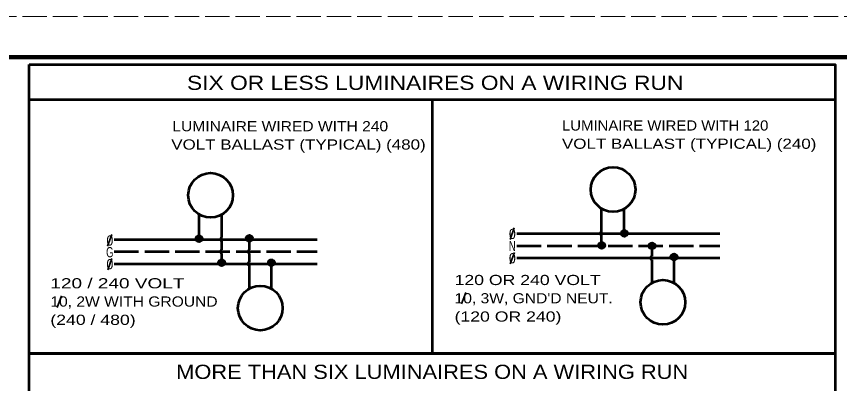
# Model space of a CAD drawing. Extents: x -153 to 527, y -247 to 194.
# Drawn here: x 197.9 to 400.8, y 103.1 to 193.5 of the extents above; entities that cross this region are included whole.
import ezdxf

# ---------------------------------------------------------------- set-up
doc = ezdxf.new("R2010")
doc.units = 0
doc.linetypes.add('LONG_DASHED', pattern=[7.5, 6, -1.5])
doc.layers.add('1', color=7, linetype='Continuous', lineweight=53)
doc.layers.add('61', color=7, linetype='Continuous', lineweight=35)

msp = doc.modelspace()

# ---------------------------------------------------------------- linework, layer by layer
at = {"layer": '1'}
for p, q in [((201.088, 173.059), (399.686, 173.059)), ((300.387, 173.059), (300.387, 110.53)), ((342.12, 140.506), (342.12, 146.192)), ((347.698, 140.106), (347.698, 146.107)), ((242.98, 138.664), (242.98, 144.723)), ((242.98, 138.664), (242.98, 144.723)), ((248.545, 139.064), (248.545, 144.723)), ((248.545, 139.064), (248.545, 144.723)), ((321.267, 140.03), (371.267, 140.03)), ((222.049, 138.608), (272.049, 138.608)), ((222.049, 138.608), (272.049, 138.608)), ((248.545, 136.045), (248.545, 138.189)), ((255.303, 138.425), (255.303, 136.047)), ((342.134, 137.482), (342.134, 139.626)), ((354.521, 137.498), (354.521, 137.469)), ((354.521, 136.589), (354.521, 134.445)), ((248.545, 132.787), (248.545, 135.165)), ((248.545, 132.787), (248.545, 135.165)), ((255.303, 135.167), (255.303, 133.023)), ((321.267, 134.03), (371.267, 134.03)), ((360.029, 127.865), (360.029, 134.05)), ((222.049, 132.608), (272.049, 132.608)), ((222.049, 132.608), (272.049, 132.608)), ((255.303, 132.148), (255.303, 126.489)), ((255.303, 132.148), (255.303, 126.489)), ((260.811, 126.443), (260.811, 132.628)), ((260.811, 126.443), (260.811, 132.628)), ((354.521, 133.57), (354.521, 127.911))]:
    msp.add_line(p, q, dxfattribs=at)
at = {"layer": '1', "lineweight": 35}
for p, q in [((320.609, 141.457), (319.578, 138.624)), ((221.415, 139.799), (220.384, 136.967)), ((221.465, 133.941), (220.434, 131.108)), ((320.658, 135.4), (319.627, 132.567)), ((209.004, 124.707), (207.973, 121.875)), ((308.644, 125.57), (307.613, 122.737))]:
    msp.add_line(p, q, dxfattribs=at)
at = {"layer": '1', "linetype": 'LONG_DASHED'}
for p, q in [((321.267, 137.03), (371.267, 137.03)), ((222.049, 135.608), (272.049, 135.608)), ((222.049, 135.608), (272.049, 135.608))]:
    msp.add_line(p, q, dxfattribs=at)
at = {"layer": '1'}
for points in [[(201.088, 181.71), (399.686, 181.71), (399.686, 110.53), (201.088, 110.53)], [(201.088, 110.53), (399.686, 110.53), (399.686, 11.168), (201.088, 11.168)]]:
    msp.add_lwpolyline(points, close=True, dxfattribs=at)
for centre, radius in [((344.981, 150.889), 5.5), ((245.763, 149.467), 5.5), ((245.763, 149.467), 5.5), ((342.028, 140.36), 0.0208), ((347.779, 140.088), 0.75), ((347.779, 140.102), 0.724), ((347.779, 140.088), 0.698), ((347.772, 140.088), 0.67), ((347.765, 140.102), 0.636), ((347.755, 140.126), 0.606), ((347.745, 140.143), 0.575), ((347.741, 140.157), 0.55), ((347.734, 140.146), 0.517), ((347.728, 140.163), 0.482), ((347.721, 140.157), 0.455), ((347.71, 140.191), 0.424), ((347.704, 140.198), 0.397), ((347.69, 140.204), 0.357), ((347.693, 140.204), 0.333), ((347.687, 140.232), 0.297), ((347.676, 140.249), 0.267), ((347.673, 140.256), 0.236), ((347.669, 140.259), 0.205), ((347.659, 140.259), 0.174), ((347.645, 140.262), 0.133), ((347.645, 140.262), 0.0993), ((347.649, 140.259), 0.0548), ((242.947, 138.759), 0.75), ((242.947, 138.759), 0.75), ((242.947, 138.773), 0.724), ((242.947, 138.773), 0.724), ((242.947, 138.76), 0.698), ((242.947, 138.76), 0.698), ((242.94, 138.76), 0.67), ((242.933, 138.773), 0.636), ((242.923, 138.797), 0.606), ((242.913, 138.814), 0.575), ((242.909, 138.828), 0.55), ((242.902, 138.818), 0.517), ((242.895, 138.835), 0.482), ((242.889, 138.828), 0.455), ((242.878, 138.862), 0.424), ((242.872, 138.869), 0.397), ((242.858, 138.876), 0.357), ((242.861, 138.876), 0.333), ((242.854, 138.903), 0.297), ((242.844, 138.92), 0.267), ((242.841, 138.927), 0.236), ((242.837, 138.931), 0.205), ((242.827, 138.931), 0.174), ((242.813, 138.934), 0.133), ((242.813, 138.934), 0.0993), ((242.817, 138.931), 0.0548), ((242.81, 138.937), 0.0208), ((255.326, 138.873), 0.75), ((255.326, 138.873), 0.75), ((255.326, 138.887), 0.724), ((255.326, 138.887), 0.724), ((255.326, 138.873), 0.698), ((255.326, 138.873), 0.698), ((255.319, 138.873), 0.67), ((255.312, 138.887), 0.636), ((255.302, 138.911), 0.606), ((255.292, 138.928), 0.575), ((255.288, 138.942), 0.55), ((255.281, 138.931), 0.517), ((255.275, 138.948), 0.482), ((255.268, 138.942), 0.455), ((255.258, 138.976), 0.424), ((255.251, 138.983), 0.397), ((255.237, 138.989), 0.357), ((255.24, 138.989), 0.333), ((255.234, 139.017), 0.297), ((255.223, 139.034), 0.267), ((255.22, 139.041), 0.236), ((255.216, 139.044), 0.205), ((255.206, 139.044), 0.174), ((255.193, 139.048), 0.133), ((255.193, 139.048), 0.0993), ((255.196, 139.044), 0.0548), ((255.189, 139.051), 0.0208), ((342.164, 137.125), 0.75), ((342.164, 137.139), 0.724), ((342.164, 137.125), 0.698), ((342.158, 137.125), 0.67), ((342.151, 137.139), 0.636), ((342.14, 137.163), 0.606), ((342.13, 137.18), 0.575), ((342.127, 137.194), 0.55), ((342.12, 137.183), 0.517), ((342.113, 137.2), 0.482), ((342.106, 137.194), 0.455), ((342.096, 137.228), 0.424), ((342.089, 137.234), 0.397), ((342.076, 137.241), 0.357), ((342.079, 137.241), 0.333), ((342.072, 137.269), 0.297), ((342.062, 137.286), 0.267), ((342.058, 137.293), 0.236), ((342.055, 137.296), 0.205), ((342.045, 137.296), 0.174), ((342.031, 137.299), 0.133), ((342.031, 137.299), 0.0993), ((342.034, 137.296), 0.0548), ((354.575, 137.02), 0.75), ((354.575, 137.034), 0.724), ((354.575, 137.02), 0.698), ((354.568, 137.02), 0.67), ((354.561, 137.034), 0.636), ((354.551, 137.058), 0.606), ((354.541, 137.075), 0.575), ((354.537, 137.089), 0.55), ((354.53, 137.078), 0.517), ((354.523, 137.096), 0.482), ((354.517, 137.089), 0.455), ((354.506, 137.123), 0.424), ((354.5, 137.13), 0.397), ((354.486, 137.137), 0.357), ((354.489, 137.137), 0.333), ((354.482, 137.164), 0.297), ((354.472, 137.181), 0.267), ((354.469, 137.188), 0.236), ((354.465, 137.191), 0.205), ((354.455, 137.191), 0.174), ((354.441, 137.195), 0.133), ((354.441, 137.195), 0.0993), ((354.445, 137.191), 0.0548), ((354.438, 137.198), 0.0208), ((359.995, 134.276), 0.75), ((359.995, 134.29), 0.724), ((359.995, 134.276), 0.698), ((359.988, 134.276), 0.67), ((359.981, 134.29), 0.636), ((359.971, 134.314), 0.606), ((359.961, 134.331), 0.575), ((359.957, 134.345), 0.55), ((359.95, 134.334), 0.517), ((359.944, 134.351), 0.482), ((359.937, 134.345), 0.455), ((359.926, 134.379), 0.424), ((359.92, 134.386), 0.397), ((359.906, 134.392), 0.357), ((359.909, 134.392), 0.333), ((359.903, 134.42), 0.297), ((359.892, 134.437), 0.267), ((359.889, 134.444), 0.236), ((359.885, 134.447), 0.205), ((359.875, 134.447), 0.174), ((359.861, 134.451), 0.133), ((359.861, 134.451), 0.0993), ((359.865, 134.447), 0.0548), ((359.858, 134.454), 0.0208), ((248.512, 132.854), 0.75), ((248.512, 132.854), 0.75), ((248.512, 132.868), 0.724), ((248.512, 132.868), 0.724), ((248.512, 132.854), 0.698), ((248.505, 132.854), 0.67), ((248.498, 132.868), 0.636), ((248.488, 132.892), 0.606), ((248.477, 132.909), 0.575), ((248.474, 132.922), 0.55), ((248.467, 132.912), 0.517), ((248.46, 132.929), 0.482), ((248.454, 132.922), 0.455), ((248.443, 132.957), 0.424), ((248.436, 132.963), 0.397), ((248.423, 132.97), 0.357), ((248.426, 132.97), 0.333), ((248.419, 132.998), 0.297), ((248.409, 133.015), 0.267), ((248.406, 133.022), 0.236), ((248.402, 133.025), 0.205), ((248.392, 133.025), 0.174), ((248.378, 133.028), 0.133), ((248.378, 133.028), 0.0993), ((248.382, 133.025), 0.0548), ((248.375, 133.032), 0.0208), ((260.777, 132.854), 0.75), ((260.777, 132.854), 0.75), ((260.777, 132.868), 0.724), ((260.777, 132.868), 0.724), ((260.777, 132.854), 0.698), ((260.777, 132.854), 0.698), ((260.77, 132.854), 0.67), ((260.77, 132.854), 0.67), ((260.763, 132.868), 0.636), ((260.753, 132.892), 0.606), ((260.743, 132.909), 0.575), ((260.74, 132.922), 0.55), ((260.733, 132.912), 0.517), ((260.726, 132.929), 0.482), ((260.719, 132.922), 0.455), ((260.709, 132.957), 0.424), ((260.702, 132.963), 0.397), ((260.688, 132.97), 0.357), ((260.692, 132.97), 0.333), ((260.685, 132.998), 0.297), ((260.675, 133.015), 0.267), ((260.671, 133.022), 0.236), ((260.668, 133.025), 0.205), ((260.657, 133.025), 0.174), ((260.644, 133.028), 0.133), ((260.644, 133.028), 0.0993), ((260.647, 133.025), 0.0548), ((260.64, 133.032), 0.0208), ((357.246, 123.121), 5.5), ((258.029, 121.699), 5.5), ((258.029, 121.699), 5.5)]:
    msp.add_circle(centre, radius, dxfattribs=at)
for centre in [(342.271, 140.066), (248.682, 138.629), (248.682, 138.629), (248.71, 135.605), (255.468, 135.607), (255.468, 135.607), (354.685, 137.029), (354.657, 134.005), (255.439, 132.583), (255.439, 132.583)]:
    msp.add_arc(centre, 0.465, 108.90604, 251.09396, dxfattribs=at)
at = {"layer": '61', "linetype": 'LONG_DASHED', "lineweight": 13}
msp.add_line((-153.062, 193.509), (526.958, 193.509), dxfattribs=at)
at = {"layer": '61', "lineweight": 158}
msp.add_lwpolyline([(515.978, 183.509), (-123.062, 183.509), (-123.062, -236.511)], dxfattribs=at)

# ---------------------------------------------------------------- texts
at = {"layer": '1'}
for s, height, width, p in [('SIX OR LESS LUMINAIRES ON A WIRING RUN', 3.5, 1.2, (239.96, 175.427)), ('LUMINAIRE WIRED WITH 240', 2.5, 1.15, (236.35, 165.232)), ('LUMINAIRE WIRED WITH 120', 2.5, 1.1, (332.372, 165.415)), ('VOLT BALLAST (TYPICAL) (480)', 2.5, 1.25, (236.087, 160.732)), ('VOLT BALLAST (TYPICAL) (240)', 2.5, 1.25, (332.372, 160.915)), ('0', 2.5, 0.9, (319.315, 138.706)), ('0', 2.5, 0.9, (220.122, 137.093)), ('N', 2.5, 0.7, (319.29, 135.724)), ('G', 2.5, 0.7, (220.022, 134.211)), ('0', 2.5, 0.9, (319.315, 132.716)), ('0', 2.5, 0.9, (220.122, 131.254)), ('120 OR 240 VOLT', 2.5, 1.3, (305.907, 127.366)), ('120 / 240 VOLT', 2.5, 1.4, (206.288, 126.555)), ('10, 2W WITH GROUND', 2.5, 1.15, (206.288, 122.055)), ("10, 3W, GND'D NEUT.", 2.5, 1.15, (305.907, 122.866)), ('(240 / 480)', 2.5, 1.3, (206.288, 117.555)), ('(120 OR 240)', 2.5, 1.3, (305.907, 118.366)), ('MORE THAN SIX LUMINAIRES ON A WIRING RUN', 3.5, 1.15, (237.295, 104.248))]:
    msp.add_text(s, height=height, dxfattribs=dict(at, width=width)).set_placement(p)

doc.saveas('drawing.dxf')
